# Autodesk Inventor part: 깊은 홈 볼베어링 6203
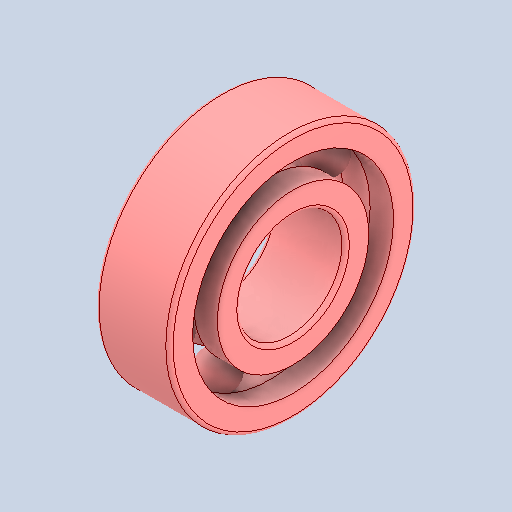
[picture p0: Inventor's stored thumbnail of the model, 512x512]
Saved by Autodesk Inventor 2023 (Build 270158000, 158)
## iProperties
Created: 2024-09
Part Number: 깊은 홈 볼베어링 6203
Material: 강철, 연강
Description: 깊은 그루브 볼 베어링
Document SubType Name: Modeling
Designer: home
Density: 7.85 g/cm^3
Appearance: 기본값
Author: jhkim
Sending System: Autodesk Inventor 2025
Preprocessor: ST-DEVELOPER v20
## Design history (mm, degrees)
feature "Solid1"
feature "Solid1:1"
feature "Solid1:2"
feature "Solid1:3"
feature "Solid1:4"
feature "Solid1:5"
feature "Solid1:6"
feature "Solid1:7"
feature "Solid1:8"
node "솔리드1"
node "솔리드2"
node "솔리드3"
node "솔리드4"
node "솔리드5"
node "솔리드6"
node "솔리드7"
node "솔리드8"
node "솔리드9"
